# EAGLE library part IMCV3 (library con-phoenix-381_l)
Invertierter Mini-Combicon 3.81mm vertikal 3-polig IMCV 1,5/3-G-3,81 (ohne Gegenstecker)
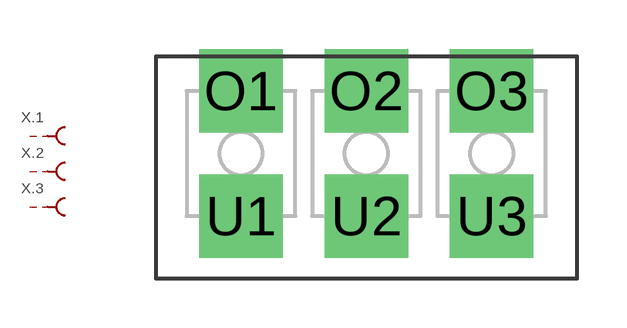
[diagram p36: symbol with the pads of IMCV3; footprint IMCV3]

Designator prefix X; gates .2=MCBU .1=MCBU .3=MCBU

## IMCV3  [IMCV3]
O1  .1:S  pas
O2  .2:S  pas
O3  .3:S  pas
U1  .1:SK  pas
U2  .2:SK  pas
U3  .3:SK  pas

## Footprint IMCV3 (pad centres in mm)
Mini-Combicon 3.81mm vertical 3-polig invertiert (ohne Gegenstecker)
drill 1.3 pad 2.54 square: O1 -3.81,1.905; O2 0,1.905; O3 3.81,1.905; U1 -3.81,-1.905; U2 0,-1.905; U3 3.81,-1.905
